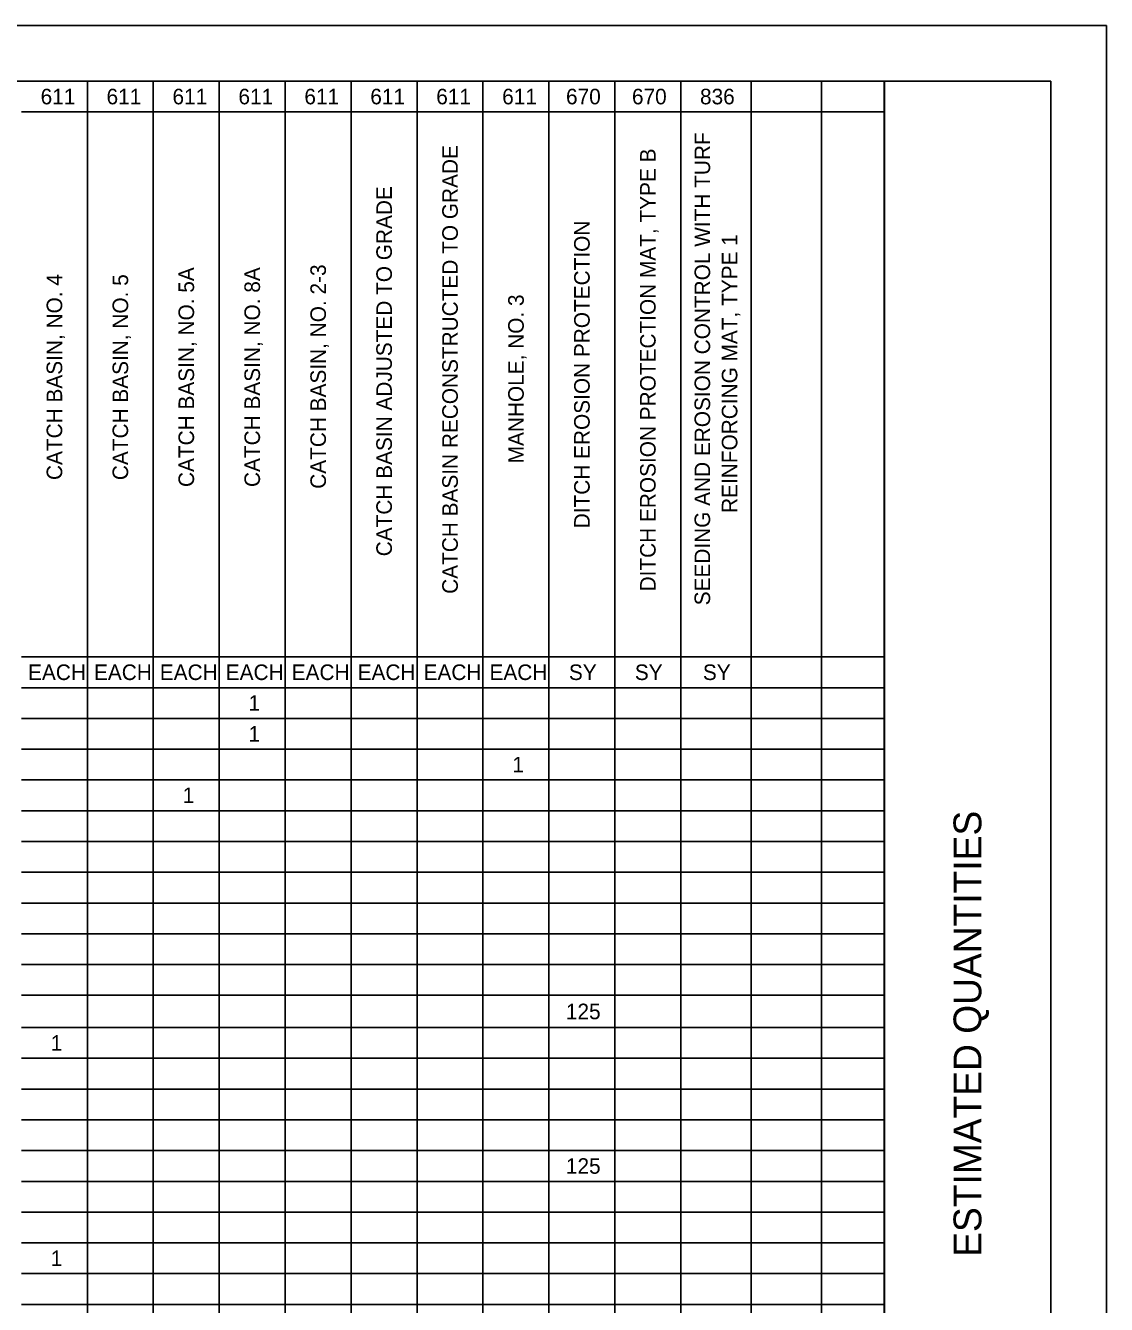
# Model space of a CAD drawing. Extents: x 0.2 to 34.2, y 0 to 22.
# Drawn here: x 24.47 to 34.19, y 10.52 to 22.03 of the extents above; entities that cross this region are included whole.
import ezdxf

# ---------------------------------------------------------------- set-up
doc = ezdxf.new("R2010")
doc.units = 0
for name, color, linetype in [('SH_Border', 7, 'Continuous'), ('SH_Cut_Line', 7, 'Continuous'), ('SH_Data', 7, 'Continuous'), ('SH_Text', 7, 'Continuous')]:
    doc.layers.add(name, color=color, linetype=linetype)

msp = doc.modelspace()

# ---------------------------------------------------------------- linework, layer by layer
at = {"layer": 'SH_Border'}
msp.add_line((32.192, 0.525), (32.192, 21.525), dxfattribs=at)
msp.add_lwpolyline([(1.692, 21.525), (33.692, 21.525), (33.692, 0.525), (1.692, 0.525)], close=True, dxfattribs=at)
at = {"layer": 'SH_Cut_Line'}
msp.add_lwpolyline([(0.192, 0.025), (34.192, 0.025), (34.192, 22.025), (0.192, 22.025)], close=True, dxfattribs=at)
at = {"layer": 'SH_Text'}
for p, q in [((24.435, 21.525), (32.196, 21.525)), ((25.028, 21.525), (25.028, 21.249)), ((25.62, 21.525), (25.62, 21.249)), ((26.213, 21.525), (26.213, 21.249)), ((26.806, 21.525), (26.806, 21.249)), ((27.399, 21.525), (27.399, 21.249)), ((27.992, 21.525), (27.992, 21.249)), ((28.585, 21.525), (28.585, 21.249)), ((29.178, 21.525), (29.178, 21.249)), ((29.771, 21.525), (29.771, 21.249)), ((30.364, 21.525), (30.364, 21.249)), ((30.996, 21.525), (30.996, 21.249)), ((31.629, 21.525), (31.629, 21.249)), ((32.196, 21.525), (32.196, 21.249)), ((24.435, 21.249), (32.196, 21.249)), ((25.028, 21.249), (25.028, 20.972)), ((25.62, 21.249), (25.62, 20.972)), ((26.213, 21.249), (26.213, 20.972)), ((26.806, 21.249), (26.806, 20.972)), ((27.399, 21.249), (27.399, 20.972)), ((27.992, 21.249), (27.992, 20.972)), ((28.585, 21.249), (28.585, 20.972)), ((29.178, 21.249), (29.178, 20.972)), ((29.771, 21.249), (29.771, 20.972)), ((30.364, 21.249), (30.364, 20.972)), ((30.996, 21.249), (30.996, 20.972)), ((31.629, 21.249), (31.629, 20.972)), ((32.196, 21.249), (32.196, 20.972)), ((25.028, 20.972), (25.028, 20.695)), ((25.62, 20.972), (25.62, 20.695)), ((26.213, 20.972), (26.213, 20.695)), ((26.806, 20.972), (26.806, 20.695)), ((27.399, 20.972), (27.399, 20.695)), ((27.992, 20.972), (27.992, 20.695)), ((28.585, 20.972), (28.585, 20.695)), ((29.178, 20.972), (29.178, 20.695)), ((29.771, 20.972), (29.771, 20.695)), ((30.364, 20.972), (30.364, 20.695)), ((30.996, 20.972), (30.996, 20.695)), ((31.629, 20.972), (31.629, 20.695)), ((32.196, 20.972), (32.196, 20.695)), ((25.028, 20.695), (25.028, 20.418)), ((25.62, 20.695), (25.62, 20.418)), ((26.213, 20.695), (26.213, 20.418)), ((26.806, 20.695), (26.806, 20.418)), ((27.399, 20.695), (27.399, 20.418)), ((27.992, 20.695), (27.992, 20.418)), ((28.585, 20.695), (28.585, 20.418)), ((29.178, 20.695), (29.178, 20.418)), ((29.771, 20.695), (29.771, 20.418)), ((30.364, 20.695), (30.364, 20.418)), ((30.996, 20.695), (30.996, 20.418)), ((31.629, 20.695), (31.629, 20.418)), ((32.196, 20.695), (32.196, 20.418)), ((25.028, 20.418), (25.028, 20.142)), ((25.62, 20.418), (25.62, 20.142)), ((26.213, 20.418), (26.213, 20.142)), ((26.806, 20.418), (26.806, 20.142)), ((27.399, 20.418), (27.399, 20.142)), ((27.992, 20.418), (27.992, 20.142)), ((28.585, 20.418), (28.585, 20.142)), ((29.178, 20.418), (29.178, 20.142)), ((29.771, 20.418), (29.771, 20.142)), ((30.364, 20.418), (30.364, 20.142)), ((30.996, 20.418), (30.996, 20.142)), ((31.629, 20.418), (31.629, 20.142)), ((32.196, 20.418), (32.196, 20.142)), ((25.028, 20.142), (25.028, 19.865)), ((25.62, 20.142), (25.62, 19.865)), ((26.213, 20.142), (26.213, 19.865)), ((26.806, 20.142), (26.806, 19.865)), ((27.399, 20.142), (27.399, 19.865)), ((27.992, 20.142), (27.992, 19.865)), ((28.585, 20.142), (28.585, 19.865)), ((29.178, 20.142), (29.178, 19.865)), ((29.771, 20.142), (29.771, 19.865)), ((30.364, 20.142), (30.364, 19.865)), ((30.996, 20.142), (30.996, 19.865)), ((31.629, 20.142), (31.629, 19.865)), ((32.196, 20.142), (32.196, 19.865)), ((25.028, 19.865), (25.028, 19.588)), ((25.62, 19.865), (25.62, 19.588)), ((26.213, 19.865), (26.213, 19.588)), ((26.806, 19.865), (26.806, 19.588)), ((27.399, 19.865), (27.399, 19.588)), ((27.992, 19.865), (27.992, 19.588)), ((28.585, 19.865), (28.585, 19.588)), ((29.178, 19.865), (29.178, 19.588)), ((29.771, 19.865), (29.771, 19.588)), ((30.364, 19.865), (30.364, 19.588)), ((30.996, 19.865), (30.996, 19.588)), ((31.629, 19.865), (31.629, 19.588)), ((32.196, 19.865), (32.196, 19.588)), ((25.028, 19.588), (25.028, 19.312)), ((25.62, 19.588), (25.62, 19.312)), ((26.213, 19.588), (26.213, 19.312)), ((26.806, 19.588), (26.806, 19.312)), ((27.399, 19.588), (27.399, 19.312)), ((27.992, 19.588), (27.992, 19.312)), ((28.585, 19.588), (28.585, 19.312)), ((29.178, 19.588), (29.178, 19.312)), ((29.771, 19.588), (29.771, 19.312)), ((30.364, 19.588), (30.364, 19.312)), ((30.996, 19.588), (30.996, 19.312)), ((31.629, 19.588), (31.629, 19.312)), ((32.196, 19.588), (32.196, 19.312)), ((25.028, 19.312), (25.028, 19.035)), ((25.62, 19.312), (25.62, 19.035)), ((26.213, 19.312), (26.213, 19.035)), ((26.806, 19.312), (26.806, 19.035)), ((27.399, 19.312), (27.399, 19.035)), ((27.992, 19.312), (27.992, 19.035)), ((28.585, 19.312), (28.585, 19.035)), ((29.178, 19.312), (29.178, 19.035)), ((29.771, 19.312), (29.771, 19.035)), ((30.364, 19.312), (30.364, 19.035)), ((30.996, 19.312), (30.996, 19.035)), ((31.629, 19.312), (31.629, 19.035)), ((32.196, 19.312), (32.196, 19.035)), ((25.028, 19.035), (25.028, 18.758)), ((25.62, 19.035), (25.62, 18.758)), ((26.213, 19.035), (26.213, 18.758)), ((26.806, 19.035), (26.806, 18.758)), ((27.399, 19.035), (27.399, 18.758)), ((27.992, 19.035), (27.992, 18.758)), ((28.585, 19.035), (28.585, 18.758)), ((29.178, 19.035), (29.178, 18.758)), ((29.771, 19.035), (29.771, 18.758)), ((30.364, 19.035), (30.364, 18.758)), ((30.996, 19.035), (30.996, 18.758)), ((31.629, 19.035), (31.629, 18.758)), ((32.196, 19.035), (32.196, 18.758)), ((25.028, 18.758), (25.028, 18.482)), ((25.62, 18.758), (25.62, 18.482)), ((26.213, 18.758), (26.213, 18.482)), ((26.806, 18.758), (26.806, 18.482)), ((27.399, 18.758), (27.399, 18.482)), ((27.992, 18.758), (27.992, 18.482)), ((28.585, 18.758), (28.585, 18.482)), ((29.178, 18.758), (29.178, 18.482)), ((29.771, 18.758), (29.771, 18.482)), ((30.364, 18.758), (30.364, 18.482)), ((30.996, 18.758), (30.996, 18.482)), ((31.629, 18.758), (31.629, 18.482)), ((32.196, 18.758), (32.196, 18.482)), ((25.028, 18.482), (25.028, 18.205)), ((25.62, 18.482), (25.62, 18.205)), ((26.213, 18.482), (26.213, 18.205)), ((26.806, 18.482), (26.806, 18.205)), ((27.399, 18.482), (27.399, 18.205)), ((27.992, 18.482), (27.992, 18.205)), ((28.585, 18.482), (28.585, 18.205)), ((29.178, 18.482), (29.178, 18.205)), ((29.771, 18.482), (29.771, 18.205)), ((30.364, 18.482), (30.364, 18.205)), ((30.996, 18.482), (30.996, 18.205)), ((31.629, 18.482), (31.629, 18.205)), ((32.196, 18.482), (32.196, 18.205)), ((25.028, 18.205), (25.028, 16.347)), ((25.62, 18.205), (25.62, 16.347)), ((26.213, 18.205), (26.213, 16.347)), ((26.806, 18.205), (26.806, 16.347)), ((27.399, 18.205), (27.399, 16.347)), ((27.992, 18.205), (27.992, 16.347)), ((28.585, 18.205), (28.585, 16.347)), ((29.178, 18.205), (29.178, 16.347)), ((29.771, 18.205), (29.771, 16.347)), ((30.364, 18.205), (30.364, 16.347)), ((30.996, 18.205), (30.996, 16.347)), ((31.629, 18.205), (31.629, 16.347)), ((32.196, 18.205), (32.196, 16.347)), ((24.435, 16.347), (32.196, 16.347)), ((25.028, 16.347), (25.028, 16.07)), ((25.62, 16.347), (25.62, 16.07)), ((26.213, 16.347), (26.213, 16.07)), ((26.806, 16.347), (26.806, 16.07)), ((27.399, 16.347), (27.399, 16.07)), ((27.992, 16.347), (27.992, 16.07)), ((28.585, 16.347), (28.585, 16.07)), ((29.178, 16.347), (29.178, 16.07)), ((29.771, 16.347), (29.771, 16.07)), ((30.364, 16.347), (30.364, 16.07)), ((30.996, 16.347), (30.996, 16.07)), ((31.629, 16.347), (31.629, 16.07)), ((32.196, 16.347), (32.196, 16.07)), ((24.435, 16.07), (32.196, 16.07)), ((25.028, 16.07), (25.028, 15.794)), ((25.62, 16.07), (25.62, 15.794)), ((26.213, 16.07), (26.213, 15.794)), ((26.806, 16.07), (26.806, 15.794)), ((27.399, 16.07), (27.399, 15.794)), ((27.992, 16.07), (27.992, 15.794)), ((28.585, 16.07), (28.585, 15.794)), ((29.178, 16.07), (29.178, 15.794)), ((29.771, 16.07), (29.771, 15.794)), ((30.364, 16.07), (30.364, 15.794)), ((30.996, 16.07), (30.996, 15.794)), ((31.629, 16.07), (31.629, 15.794)), ((32.196, 16.07), (32.196, 15.794)), ((24.435, 15.794), (32.196, 15.794)), ((25.028, 15.794), (25.028, 15.517)), ((25.62, 15.794), (25.62, 15.517)), ((26.213, 15.794), (26.213, 15.517)), ((26.806, 15.794), (26.806, 15.517)), ((27.399, 15.794), (27.399, 15.517)), ((27.992, 15.794), (27.992, 15.517)), ((28.585, 15.794), (28.585, 15.517)), ((29.178, 15.794), (29.178, 15.517)), ((29.771, 15.794), (29.771, 15.517)), ((30.364, 15.794), (30.364, 15.517)), ((30.996, 15.794), (30.996, 15.517)), ((31.629, 15.794), (31.629, 15.517)), ((32.196, 15.794), (32.196, 15.517)), ((24.435, 15.517), (32.196, 15.517)), ((25.028, 15.517), (25.028, 15.24)), ((25.62, 15.517), (25.62, 15.24)), ((26.213, 15.517), (26.213, 15.24)), ((26.806, 15.517), (26.806, 15.24)), ((27.399, 15.517), (27.399, 15.24)), ((27.992, 15.517), (27.992, 15.24)), ((28.585, 15.517), (28.585, 15.24)), ((29.178, 15.517), (29.178, 15.24)), ((29.771, 15.517), (29.771, 15.24)), ((30.364, 15.517), (30.364, 15.24)), ((30.996, 15.517), (30.996, 15.24)), ((31.629, 15.517), (31.629, 15.24)), ((32.196, 15.517), (32.196, 15.24)), ((24.435, 15.24), (32.196, 15.24)), ((25.028, 15.24), (25.028, 14.963)), ((25.62, 15.24), (25.62, 14.963)), ((26.213, 15.24), (26.213, 14.963)), ((26.806, 15.24), (26.806, 14.963)), ((27.399, 15.24), (27.399, 14.963)), ((27.992, 15.24), (27.992, 14.963)), ((28.585, 15.24), (28.585, 14.963)), ((29.178, 15.24), (29.178, 14.963)), ((29.771, 15.24), (29.771, 14.963)), ((30.364, 15.24), (30.364, 14.963)), ((30.996, 15.24), (30.996, 14.963)), ((31.629, 15.24), (31.629, 14.963)), ((32.196, 15.24), (32.196, 14.963)), ((24.435, 14.963), (32.196, 14.963)), ((25.028, 14.963), (25.028, 14.687)), ((25.62, 14.963), (25.62, 14.687)), ((26.213, 14.963), (26.213, 14.687)), ((26.806, 14.963), (26.806, 14.687)), ((27.399, 14.963), (27.399, 14.687)), ((27.992, 14.963), (27.992, 14.687)), ((28.585, 14.963), (28.585, 14.687)), ((29.178, 14.963), (29.178, 14.687)), ((29.771, 14.963), (29.771, 14.687)), ((30.364, 14.963), (30.364, 14.687)), ((30.996, 14.963), (30.996, 14.687)), ((31.629, 14.963), (31.629, 14.687)), ((32.196, 14.963), (32.196, 14.687)), ((24.435, 14.687), (32.196, 14.687)), ((25.028, 14.687), (25.028, 14.41)), ((25.62, 14.687), (25.62, 14.41)), ((26.213, 14.687), (26.213, 14.41)), ((26.806, 14.687), (26.806, 14.41)), ((27.399, 14.687), (27.399, 14.41)), ((27.992, 14.687), (27.992, 14.41)), ((28.585, 14.687), (28.585, 14.41)), ((29.178, 14.687), (29.178, 14.41)), ((29.771, 14.687), (29.771, 14.41)), ((30.364, 14.687), (30.364, 14.41)), ((30.996, 14.687), (30.996, 14.41)), ((31.629, 14.687), (31.629, 14.41)), ((32.196, 14.687), (32.196, 14.41)), ((24.435, 14.41), (32.196, 14.41)), ((25.028, 14.41), (25.028, 14.133)), ((25.62, 14.41), (25.62, 14.133)), ((26.213, 14.41), (26.213, 14.133)), ((26.806, 14.41), (26.806, 14.133)), ((27.399, 14.41), (27.399, 14.133)), ((27.992, 14.41), (27.992, 14.133)), ((28.585, 14.41), (28.585, 14.133)), ((29.178, 14.41), (29.178, 14.133)), ((29.771, 14.41), (29.771, 14.133)), ((30.364, 14.41), (30.364, 14.133)), ((30.996, 14.41), (30.996, 14.133)), ((31.629, 14.41), (31.629, 14.133)), ((32.196, 14.41), (32.196, 14.133)), ((24.435, 14.133), (32.196, 14.133)), ((25.028, 14.133), (25.028, 13.857)), ((25.62, 14.133), (25.62, 13.857)), ((26.213, 14.133), (26.213, 13.857)), ((26.806, 14.133), (26.806, 13.857)), ((27.399, 14.133), (27.399, 13.857)), ((27.992, 14.133), (27.992, 13.857)), ((28.585, 14.133), (28.585, 13.857)), ((29.178, 14.133), (29.178, 13.857)), ((29.771, 14.133), (29.771, 13.857)), ((30.364, 14.133), (30.364, 13.857)), ((30.996, 14.133), (30.996, 13.857)), ((31.629, 14.133), (31.629, 13.857)), ((32.196, 14.133), (32.196, 13.857)), ((24.435, 13.857), (32.196, 13.857)), ((25.028, 13.857), (25.028, 13.58)), ((25.62, 13.857), (25.62, 13.58)), ((26.213, 13.857), (26.213, 13.58)), ((26.806, 13.857), (26.806, 13.58)), ((27.399, 13.857), (27.399, 13.58)), ((27.992, 13.857), (27.992, 13.58)), ((28.585, 13.857), (28.585, 13.58)), ((29.178, 13.857), (29.178, 13.58)), ((29.771, 13.857), (29.771, 13.58)), ((30.364, 13.857), (30.364, 13.58)), ((30.996, 13.857), (30.996, 13.58)), ((31.629, 13.857), (31.629, 13.58)), ((32.196, 13.857), (32.196, 13.58)), ((24.435, 13.58), (32.196, 13.58)), ((25.028, 13.58), (25.028, 13.303)), ((25.62, 13.58), (25.62, 13.303)), ((26.213, 13.58), (26.213, 13.303)), ((26.806, 13.58), (26.806, 13.303)), ((27.399, 13.58), (27.399, 13.303)), ((27.992, 13.58), (27.992, 13.303)), ((28.585, 13.58), (28.585, 13.303)), ((29.178, 13.58), (29.178, 13.303)), ((29.771, 13.58), (29.771, 13.303)), ((30.364, 13.58), (30.364, 13.303)), ((30.996, 13.58), (30.996, 13.303)), ((31.629, 13.58), (31.629, 13.303)), ((32.196, 13.58), (32.196, 13.303)), ((24.435, 13.303), (32.196, 13.303)), ((25.028, 13.303), (25.028, 13.013)), ((25.62, 13.303), (25.62, 13.013)), ((26.213, 13.303), (26.213, 13.013)), ((26.806, 13.303), (26.806, 13.013)), ((27.399, 13.303), (27.399, 13.013)), ((27.992, 13.303), (27.992, 13.013)), ((28.585, 13.303), (28.585, 13.013)), ((29.178, 13.303), (29.178, 13.013)), ((29.771, 13.303), (29.771, 13.013)), ((30.364, 13.303), (30.364, 13.013)), ((30.996, 13.303), (30.996, 13.013)), ((31.629, 13.303), (31.629, 13.013)), ((32.196, 13.303), (32.196, 13.013)), ((24.435, 13.013), (32.196, 13.013)), ((25.028, 13.013), (25.028, 12.737)), ((25.62, 13.013), (25.62, 12.737)), ((26.213, 13.013), (26.213, 12.737)), ((26.806, 13.013), (26.806, 12.737)), ((27.399, 13.013), (27.399, 12.737)), ((27.992, 13.013), (27.992, 12.737)), ((28.585, 13.013), (28.585, 12.737)), ((29.178, 13.013), (29.178, 12.737)), ((29.771, 13.013), (29.771, 12.737)), ((30.364, 13.013), (30.364, 12.737)), ((30.996, 13.013), (30.996, 12.737)), ((31.629, 13.013), (31.629, 12.737)), ((32.196, 13.013), (32.196, 12.737)), ((24.435, 12.737), (32.196, 12.737)), ((25.028, 12.737), (25.028, 12.46)), ((25.62, 12.737), (25.62, 12.46)), ((26.213, 12.737), (26.213, 12.46)), ((26.806, 12.737), (26.806, 12.46)), ((27.399, 12.737), (27.399, 12.46)), ((27.992, 12.737), (27.992, 12.46)), ((28.585, 12.737), (28.585, 12.46)), ((29.178, 12.737), (29.178, 12.46)), ((29.771, 12.737), (29.771, 12.46)), ((30.364, 12.737), (30.364, 12.46)), ((30.996, 12.737), (30.996, 12.46)), ((31.629, 12.737), (31.629, 12.46)), ((32.196, 12.737), (32.196, 12.46)), ((24.435, 12.46), (32.196, 12.46)), ((25.028, 12.46), (25.028, 12.183)), ((25.62, 12.46), (25.62, 12.183)), ((26.213, 12.46), (26.213, 12.183)), ((26.806, 12.46), (26.806, 12.183)), ((27.399, 12.46), (27.399, 12.183)), ((27.992, 12.46), (27.992, 12.183)), ((28.585, 12.46), (28.585, 12.183)), ((29.178, 12.46), (29.178, 12.183)), ((29.771, 12.46), (29.771, 12.183)), ((30.364, 12.46), (30.364, 12.183)), ((30.996, 12.46), (30.996, 12.183)), ((31.629, 12.46), (31.629, 12.183)), ((32.196, 12.46), (32.196, 12.183)), ((24.435, 12.183), (32.196, 12.183)), ((25.028, 12.183), (25.028, 11.906)), ((25.62, 12.183), (25.62, 11.906)), ((26.213, 12.183), (26.213, 11.906)), ((26.806, 12.183), (26.806, 11.906)), ((27.399, 12.183), (27.399, 11.906)), ((27.992, 12.183), (27.992, 11.906)), ((28.585, 12.183), (28.585, 11.906)), ((29.178, 12.183), (29.178, 11.906)), ((29.771, 12.183), (29.771, 11.906)), ((30.364, 12.183), (30.364, 11.906)), ((30.996, 12.183), (30.996, 11.906)), ((31.629, 12.183), (31.629, 11.906)), ((32.196, 12.183), (32.196, 11.906)), ((24.435, 11.906), (32.196, 11.906)), ((25.028, 11.906), (25.028, 11.63)), ((25.62, 11.906), (25.62, 11.63)), ((26.213, 11.906), (26.213, 11.63)), ((26.806, 11.906), (26.806, 11.63)), ((27.399, 11.906), (27.399, 11.63)), ((27.992, 11.906), (27.992, 11.63)), ((28.585, 11.906), (28.585, 11.63)), ((29.178, 11.906), (29.178, 11.63)), ((29.771, 11.906), (29.771, 11.63)), ((30.364, 11.906), (30.364, 11.63)), ((30.996, 11.906), (30.996, 11.63)), ((31.629, 11.906), (31.629, 11.63)), ((32.196, 11.906), (32.196, 11.63)), ((24.435, 11.63), (32.196, 11.63)), ((25.028, 11.63), (25.028, 11.353)), ((25.62, 11.63), (25.62, 11.353)), ((26.213, 11.63), (26.213, 11.353)), ((26.806, 11.63), (26.806, 11.353)), ((27.399, 11.63), (27.399, 11.353)), ((27.992, 11.63), (27.992, 11.353)), ((28.585, 11.63), (28.585, 11.353)), ((29.178, 11.63), (29.178, 11.353)), ((29.771, 11.63), (29.771, 11.353)), ((30.364, 11.63), (30.364, 11.353)), ((30.996, 11.63), (30.996, 11.353)), ((31.629, 11.63), (31.629, 11.353)), ((32.196, 11.63), (32.196, 11.353)), ((24.435, 11.353), (32.196, 11.353)), ((25.028, 11.353), (25.028, 11.076)), ((25.62, 11.353), (25.62, 11.076)), ((26.213, 11.353), (26.213, 11.076)), ((26.806, 11.353), (26.806, 11.076)), ((27.399, 11.353), (27.399, 11.076)), ((27.992, 11.353), (27.992, 11.076)), ((28.585, 11.353), (28.585, 11.076)), ((29.178, 11.353), (29.178, 11.076)), ((29.771, 11.353), (29.771, 11.076)), ((30.364, 11.353), (30.364, 11.076)), ((30.996, 11.353), (30.996, 11.076)), ((31.629, 11.353), (31.629, 11.076)), ((32.196, 11.353), (32.196, 11.076)), ((24.435, 11.076), (32.196, 11.076)), ((25.028, 11.076), (25.028, 10.8)), ((25.62, 11.076), (25.62, 10.8)), ((26.213, 11.076), (26.213, 10.8)), ((26.806, 11.076), (26.806, 10.8)), ((27.399, 11.076), (27.399, 10.8)), ((27.992, 11.076), (27.992, 10.8)), ((28.585, 11.076), (28.585, 10.8)), ((29.178, 11.076), (29.178, 10.8)), ((29.771, 11.076), (29.771, 10.8)), ((30.364, 11.076), (30.364, 10.8)), ((30.996, 11.076), (30.996, 10.8)), ((31.629, 11.076), (31.629, 10.8)), ((32.196, 11.076), (32.196, 10.8)), ((24.435, 10.8), (32.196, 10.8)), ((25.028, 10.8), (25.028, 10.523)), ((25.62, 10.8), (25.62, 10.523)), ((26.213, 10.8), (26.213, 10.523)), ((26.806, 10.8), (26.806, 10.523)), ((27.399, 10.8), (27.399, 10.523)), ((27.992, 10.8), (27.992, 10.523)), ((28.585, 10.8), (28.585, 10.523)), ((29.178, 10.8), (29.178, 10.523)), ((29.771, 10.8), (29.771, 10.523)), ((30.364, 10.8), (30.364, 10.523)), ((30.996, 10.8), (30.996, 10.523)), ((31.629, 10.8), (31.629, 10.523)), ((32.196, 10.8), (32.196, 10.523)), ((24.435, 10.523), (32.196, 10.523)), ((25.028, 10.523), (25.028, 10.233)), ((25.62, 10.523), (25.62, 10.233)), ((26.213, 10.523), (26.213, 10.233)), ((26.806, 10.523), (26.806, 10.233)), ((27.399, 10.523), (27.399, 10.233)), ((27.992, 10.523), (27.992, 10.233)), ((28.585, 10.523), (28.585, 10.233)), ((29.178, 10.523), (29.178, 10.233)), ((29.771, 10.523), (29.771, 10.233)), ((30.364, 10.523), (30.364, 10.233)), ((30.996, 10.523), (30.996, 10.233)), ((31.629, 10.523), (31.629, 10.233)), ((32.196, 10.523), (32.196, 10.233))]:
    msp.add_line(p, q, dxfattribs=at)

# ---------------------------------------------------------------- texts
at = {"layer": 'SH_Data'}
msp.add_text('ESTIMATED QUANTITIES', height=0.25, rotation=90, dxfattribs=at).set_placement((33.067, 10.951))
at = {"layer": 'SH_Text'}
for s, p in [('611', (24.607, 21.317)), ('611', (25.2, 21.317)), ('611', (25.793, 21.317)), ('611', (26.386, 21.317)), ('611', (26.979, 21.317)), ('611', (27.572, 21.317)), ('611', (28.165, 21.317)), ('611', (28.758, 21.317)), ('670', (29.332, 21.317)), ('670', (29.925, 21.317)), ('836', (30.537, 21.317)), ('EACH', (24.494, 16.139)), ('EACH', (25.087, 16.139)), ('EACH', (25.679, 16.139)), ('EACH', (26.272, 16.139)), ('EACH', (26.865, 16.139)), ('EACH', (27.458, 16.139)), ('EACH', (28.051, 16.139)), ('EACH', (28.644, 16.139)), ('SY', (29.358, 16.139)), ('SY', (29.951, 16.139)), ('SY', (30.563, 16.139)), ('1', (26.477, 15.862)), ('1', (26.477, 15.585)), ('1', (28.849, 15.308)), ('1', (25.884, 15.032)), ('125', (29.331, 13.088)), ('1', (24.698, 12.805)), ('125', (29.331, 11.698)), ('1', (24.698, 10.868))]:
    msp.add_text(s, height=0.14, dxfattribs=at).set_placement(p)
for s, p in [('SEEDING AND EROSION CONTROL WITH TURF ', (30.628, 16.811)), ('CATCH BASIN RECONSTRUCTED TO GRADE', (28.359, 16.914)), ('DITCH EROSION PROTECTION MAT, TYPE B', (30.138, 16.936)), ('CATCH BASIN ADJUSTED TO GRADE', (27.766, 17.252)), ('DITCH EROSION PROTECTION', (29.545, 17.504)), ('REINFORCING MAT, TYPE 1', (30.873, 17.642)), ('CATCH BASIN, NO. 4', (24.801, 17.938)), ('CATCH BASIN, NO. 5A', (25.987, 17.875)), ('CATCH BASIN, NO. 8A', (26.58, 17.875)), ('CATCH BASIN, NO. 2-3', (27.173, 17.859)), ('CATCH BASIN, NO. 5', (25.394, 17.937)), ('MANHOLE, NO. 3', (28.952, 18.088))]:
    msp.add_text(s, height=0.14, rotation=90, dxfattribs=at).set_placement(p)

doc.saveas('drawing.dxf')
